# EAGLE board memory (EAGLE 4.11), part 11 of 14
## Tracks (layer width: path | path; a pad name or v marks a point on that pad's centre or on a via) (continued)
N$195  (via drill 0.61) (continued)
  Top 0.254: v421,46.99 421,45.09 F07.J2 | v360.68,10.79 v360.68,6.98 | v179.71,5.71 174.62,10.79 174.62,13.97 161.93,26.67 v161.93,77.47
  Route2 0.254: v421,46.99 423.55,46.99 F07.H2
  Route3 0.254: v422.27,9.52 422.27,42.55 421,43.82 F07.J2 | v87.63,78.74 85.72,80.64 85.72,83.82 v83.82,85.72 | v50.8,113.03 50.8,145.41 53.98,148.59 53.98,214 50.8,217.17 50.8,220.34 v52.07,221.61
  Bottom 0.254: C39.R2 14.61,231.14 14.61,226.69 15.24,226.69 17.14,224.79 17.14,222.88 C39.U2 17.78,221.61 20.32,221.61 23.5,218.44 26.04,220.98 33.66,220.98 34.29,220.34 43.18,220.34 46.99,224.16 49.53,224.16 v52.07,221.61 | v422.27,9.52 421,8.25 403.86,8.25 401.95,6.35 394.97,6.35 394.33,5.71 379.1,5.71 377.82,6.98 v360.68,6.98 | v360.68,10.79 360.05,10.16 332.74,10.16 332.11,10.79 328.3,10.79 327.66,10.16 318.13,10.16 317.5,10.79 291.46,10.79 290.83,10.16 260.99,10.16 260.35,10.79 257.81,10.79 255.91,8.89 247.01,8.89 246.38,9.52 244.47,7.62 220.98,7.62 220.34,6.98 205.74,6.98 205.1,6.35 180.34,6.35 v179.71,5.71 | v161.93,77.47 160.66,78.74 v87.63,78.74 | v83.82,85.72 66.67,102.87 59.69,102.87 59.05,103.5 54.61,103.5 50.8,107.31 v50.8,113.03
N$196  (via drill 0.61)
  Route2 0.254: v373.38,37.46 382.27,46.36 388.62,46.36 394.97,52.7 403.86,52.7 404.5,52.07 413.38,52.07 417.83,56.52 420.37,56.52 F07.D2
  Route3 0.254: v233.68,8.89 233.68,7.62 205.1,7.62 199.39,1.9 141.6,1.9 53.98,89.53 53.98,105.41 60.33,111.76 60.33,114.93 59.05,116.2 59.05,116.84 60.33,118.11 60.33,143.51 63.5,146.69 63.5,200.66 64.14,201.29 64.14,209.55 63.5,210.19 63.5,254.63 60.33,257.81 60.33,280.67 57.15,283.85 57.15,293.37 55.88,294.64 B36.S2 | v255.91,10.16 259.08,10.16 259.08,9.52 260.35,8.25 307.34,8.25 309.88,10.79 327.02,10.79 327.02,16.51 330.83,20.32 337.19,20.32 344.17,27.3 353.06,27.3 353.69,26.67 362.58,26.67 v373.38,37.46
  Bottom 0.254: v233.68,8.89 234.31,8.25 243.84,8.25 245.75,10.16 v255.91,10.16
N$197  (via drill 0.61)
  Top 0.254: v316.23,5.08 311.15,10.16 311.15,35.56 309.88,36.83 309.88,40.64 F16.K2
  Route3 0.254: v375.29,5.08 379.73,0.63 421,0.63 421,10.16 415.93,15.24 415.93,37.46 419.1,40.64 419.1,48.9 417.83,50.16 v417.83,50.8
  Bottom 0.254: v316.23,5.08 316.87,5.71 341.63,5.71 342.9,4.44 374.65,4.44 v375.29,5.08 | v417.83,50.8 420.37,50.8 F07.F2
N$198
  Bottom 0.254: A05.F2 446.4,394.34 446.4,398.15 454.66,398.15 455.3,398.78 464.19,398.78 464.82,398.15 467.36,398.15 468,398.78 476.88,398.78 477.52,398.15 480.06,398.15 481.33,399.42 483.87,399.42 A02.D2
N$200
  Bottom 0.254: B36.L2 52.7,311.79 53.98,313.06 60.96,313.06 61.59,312.42 70.48,312.42 71.12,313.06 73.66,313.06 74.3,312.42 83.19,312.42 83.82,313.06 86.36,313.06 87.63,311.79 90.17,311.79 B33.L2
N$201  (via drill 0.61)
  Top 0.254: v58.42,344.17 57.15,342.9 57.15,326.39 56.52,325.75 56.52,321.95 55.88,321.31 B36.H2 | v20.95,346.08 20.32,346.71 20.32,350.52 19.05,351.79 19.05,384.81 v17.78,386.08
  Bottom 0.254: v58.42,344.17 57.78,343.54 23.5,343.54 v20.95,346.08 | v17.78,386.08 15.24,388.62 8.89,388.62 4.45,393.06 1.91,393.06 A40.F2
N$202
  Top 0.254: A37.M2 42.55,378.46 41.27,379.73 41.27,398.15 40.01,399.42 A37.D2
N$203  (via drill 0.61)
  Top 0.254: v246.38,368.3 244.47,370.21 244.47,407.04 v241.94,409.58
  Route2 0.254: v246.38,368.3 251.46,363.22 254.63,363.22 255.27,362.59 A20.T2 | v202.56,410.85 199.39,414.02 191.13,414.02 190.5,414.66 170.81,414.66 163.83,407.67 161.29,407.67 158.12,410.85 151.76,410.85 150.5,412.12 139.06,412.12 137.79,413.39 67.94,413.39 45.72,391.16 43.18,391.16 A37.H2
  Bottom 0.254: v241.94,409.58 240.03,411.48 203.2,411.48 v202.56,410.85
N$204  (via drill 0.61)
  Top 0.254: v422.27,346.71 422.27,391.8 421,393.06 A07.F2 | v480.69,350.52 483.87,353.7 483.87,354.97 A02.V2
  Bottom 0.254: v422.27,346.71 476.88,346.71 v480.69,350.52
N$205  (via drill 0.61)
  Top 0.254: v433.7,370.21 433.7,372.11 431.8,374.02 431.8,385.45 433.07,386.72 A06.J2
  Bottom 0.254: v433.7,370.21 441.96,370.21 442.6,369.57 451.49,369.57 455.3,373.38 464.19,373.38 464.82,372.75 467.36,372.75 471.17,376.56 480.06,376.56 481.33,375.29 483.87,375.29 A02.N2
N$206
  Top 0.254: F16.U2 309.25,16.51 309.25,21.59 F16.S2
  Bottom 0.254: F15.T2 318.77,19.69 314.32,19.69 312.42,21.59 309.88,21.59 F16.S2
N$207  (via drill 0.61)
  Top 0.254: v241.3,313.69 241.3,306.71 242.57,305.44 B21.N2 | v257.81,312.42 257.81,309.25 258.44,308.61 B20.M2
  Bottom 0.254: v241.3,313.69 245.75,313.69 B21.K2 246.38,313.69 248.92,313.69 250.19,312.42 v257.81,312.42
N$208  (via drill 0.61)
  Route3 0.254: v373.38,225.42 373.38,222.88 C11.U2 | v351.15,227.33 349.25,229.23 349.25,278.77 347.98,280.04 347.98,284.48 349.25,285.75 349.25,296.55 346.07,299.72 346.07,306.07 347.35,307.34 B13.M2
  Bottom 0.254: v373.38,225.42 372.11,226.69 364.49,226.69 363.86,227.33 354.96,227.33 354.33,226.69 351.79,226.69 v351.15,227.33
N$209
  Bottom 0.254: A06.L2 433.7,381.64 434.98,382.91 441.96,382.91 442.6,382.27 451.49,382.27 455.3,386.08 464.19,386.08 468,382.27 476.88,382.27 477.52,382.91 478.15,382.91 487.05,374.02 487.05,372.11 A02.P2
N$210  (via drill 0.61)
  Top 0.254: v346.07,53.98 346.07,53.34 349.25,50.16 349.25,34.29 348.62,33.66 348.62,29.84 347.98,29.21 F13.P2
  Route3 0.254: v346.07,53.98 346.07,83.18 v341.63,87.63
  Bottom 0.254: v341.63,87.63 342.26,86.99 353.06,86.99 353.69,87.63 362.58,87.63 363.22,86.99 365.76,86.99 366.39,87.63 375.29,87.63 379.1,83.82 379.73,83.82 382.9,86.99 391.16,86.99 395.61,91.44 398.14,91.44 E09.S2
N$211  (via drill 0.61)
  Top 0.254: v309.25,30.48 309.25,34.29 F16.M2
  Route3 0.254: v300.99,28.58 295.27,22.86 295.27,20.95 294,19.69 F17.T2
  Bottom 0.254: v300.99,28.58 302.89,30.48 v309.25,30.48
N$212  (via drill 0.61)
  Top 0.254: v377.19,46.36 377.82,46.99 v377.82,70.48 | v394.97,70.48 394.97,81.91 E09.V2
  Bottom 0.254: v377.19,46.36 369.57,46.36 365.76,42.55 363.22,42.55 362.58,43.18 353.69,43.18 353.06,42.55 348.62,42.55 347.98,41.91 F13.K2 | v377.82,70.48 v394.97,70.48
N$213
  Route2 0.254: A06.N2 433.7,374.02 434.98,372.75 439.42,372.75 445.77,366.4 454.66,366.4 458.47,370.21 467.36,370.21 468,369.57 476.88,369.57 477.52,370.21 480.06,370.21 481.33,368.94 483.87,368.94 A02.R2
N$214
  Bottom 0.254: F17.F2 294,51.44 294.64,52.07 299.08,52.07 299.72,52.7 302.26,52.7 302.89,52.07 304.17,52.07 305.44,53.34 309.25,53.34 F16.E2
N$215  (via drill 0.61)
  Top 0.254: v297.81,39.37 301.62,43.18 v301.62,44.45
  Route3 0.254: v297.81,39.37 297.81,36.2 297.18,35.56 F17.M2
  Bottom 0.254: v301.62,44.45 302.89,45.72 307.98,45.72 309.25,46.99 F16.H2
N$216  (via drill 0.61)
  Top 0.254: v436.25,351.79 436.25,348.62 434.98,348.62 433.7,349.89 433.7,354.97 A06.V2
  Bottom 0.254: v436.25,351.79 436.88,351.16 454.02,351.16 455.3,352.43 482.6,352.43 483.87,351.16 494.03,351.16 496.57,353.7 496.57,354.33 495.94,354.33 492.12,358.14 487.68,358.14 A02.U2
N$217  (via drill 0.61)
  Top 0.254: v325.12,73.66 327.02,75.56 327.02,99.06 v328.3,100.33 | v350.52,103.5 353.69,106.68 357.5,106.68 v357.5,104.14
  Route2 0.254: v314.32,67.31 309.25,62.23 306.7,62.23 306.7,57.79 F16.D2 | v357.5,104.14 359.41,102.23 359.41,100.33 360.68,100.33 361.95,101.6 361.95,103.5 365.76,103.5 366.39,102.87 368.3,102.87 371.48,106.04 376.56,106.04 381,110.49 381,118.74 389.89,118.74 v391.8,120.65
  Route3 0.254: v314.32,67.31 315.6,68.58 v315.6,74.29
  Bottom 0.254: v315.6,74.29 316.23,74.93 323.85,74.93 v325.12,73.66 | v328.3,100.33 334.64,100.33 337.82,103.5 340.36,103.5 341,102.87 349.88,102.87 v350.52,103.5 | v391.8,120.65 394.97,120.65 E09.F2
N$218  (via drill 0.61)
  Top 0.254: v417.19,83.18 415.93,84.45 415.93,97.16 414.02,99.06 v414.02,99.69
  Route2 0.254: v309.88,64.13 309.25,64.77 301.62,64.77 301.62,57.15 302.89,55.88 306.07,55.88 306.07,51.44 F16.F2 | v311.79,76.83 315.6,73.02 317.5,73.02 319.4,74.93 327.02,74.93 328.93,73.02 335.28,73.02 337.82,75.56 353.06,75.56 354.33,74.29 372.11,74.29 373.38,75.56 409.57,75.56 v417.19,83.18
  Route3 0.254: v309.88,64.13 312.42,66.67 312.42,76.2 v311.79,76.83 | v401.95,97.16 400.69,98.42 400.69,100.33 400.05,100.96 400.05,106.04 398.78,107.31 398.78,110.49 E09.K2
  Bottom 0.254: v414.02,99.69 408.31,99.69 405.13,96.52 402.59,96.52 v401.95,97.16
N$219  (via drill 0.61)
  Top 0.254: v276.86,5.08 269.88,12.06 269.88,36.2 268.61,37.46 F19.L2 | v329.56,4.44 v336.55,11.43 | v381,13.97 381,36.2 v381.63,36.83 | v382.27,65.41 382.9,66.04 v382.9,76.83
  Route3 0.254: v276.86,5.08 280.67,5.08 280.67,4.44 282.57,2.54 284.48,2.54 285.12,3.17 323.21,3.17 323.21,4.44 324.49,5.71 329.56,5.71 v329.56,4.44 | v381.63,36.83 381,37.46 381,64.13 v382.27,65.41 | v382.9,76.83 384.18,78.1 384.18,106.04 382.9,107.31 E10.L2
  Bottom 0.254: v336.55,11.43 337.19,10.79 359.41,10.79 363.22,14.61 365.76,14.61 366.39,13.97 375.29,13.97 375.92,14.61 378.46,14.61 379.1,13.97 v381,13.97
N$220  (via drill 0.61)
  Route3 0.254: v435.61,331.47 431.8,335.28 431.8,359.41 425.45,365.76 425.45,386.72 421,386.72 A07.J2
  Bottom 0.254: v435.61,331.47 438.79,328.3 441.96,328.3 442.6,328.93 451.49,328.93 452.12,328.3 454.66,328.3 455.3,328.93 464.19,328.93 464.82,328.3 465.45,328.3 466.73,329.56 469.9,329.56 471.17,328.3 478.79,328.3 480.06,329.56 483.87,329.56 B02.D2
N$221  (via drill 0.61)
  Top 0.254: v318.13,68.58 317.5,67.94 317.5,41.91 321.94,41.91 F15.K2 | v334.01,68.58 334.01,84.45 333.38,85.09 333.38,86.36 v335.28,88.27 | v369.57,97.79 369.57,100.96 E11.N2
  Bottom 0.254: v318.13,68.58 v334.01,68.58 | v335.28,88.27 341,93.98 349.88,93.98 350.52,93.34 353.06,93.34 356.87,97.16 365.76,97.16 366.39,96.52 368.3,96.52 v369.57,97.79
N$222  (via drill 0.61)
  Route2 0.254: v337.82,92.07 339.73,93.98 349.88,93.98 350.52,93.34 353.06,93.34 356.87,97.16 365.76,97.16 366.39,96.52 367.03,96.52 370.2,99.69 377.19,99.69 378.46,100.96 382.27,100.96 E10.N2
  Route3 0.254: v274.95,47.62 279.4,52.07 279.4,78.74 282.57,81.91 v282.57,88.9
  Bottom 0.254: v274.95,47.62 271.78,47.62 F19.H2 | v282.57,88.9 284.48,90.8 289.56,90.8 290.19,90.17 297.81,90.17 299.72,92.07 300.99,92.07 302.89,90.17 311.79,90.17 312.42,90.8 314.96,90.8 315.6,90.17 324.49,90.17 325.12,90.8 327.66,90.8 328.3,90.17 335.92,90.17 v337.82,92.07
N$223  (via drill 0.61)
  Route3 0.254: v243.21,288.29 243.21,286.39 B21.V2
  Bottom 0.254: v243.21,288.29 245.11,290.2 251.46,290.2 252.73,291.47 255.27,291.47 B20.T2
N$224
  Bottom 0.254: A06.T2 433.7,362.59 434.98,363.86 441.96,363.86 442.6,363.22 451.49,363.22 452.12,363.86 454.66,363.86 455.3,363.22 464.19,363.22 468,367.03 469.26,367.03 472.44,363.86 480.06,363.86 481.33,362.59 483.87,362.59 A02.T2
N$225  (via drill 0.61)
  Top 0.254: v321.31,29.84 321.94,30.48 321.94,34.29 F15.M2
  Bottom 0.254: v321.31,29.84 320.68,30.48 315.6,30.48 314.96,29.84 310.51,29.84 309.88,29.21 F16.P2
N$226  (via drill 0.61)
  Top 0.254: v434.98,349.89 434.98,366.4 433.7,367.67 A06.R2
  Bottom 0.254: v434.98,349.89 435.61,350.52 454.66,350.52 455.93,351.79 480.69,351.79 481.96,350.52 494.67,350.52 498.48,354.33 498.48,363.22 491.49,363.22 490.22,364.49 487.68,364.49 A02.S2
N$227  (via drill 0.61)
  Route2 0.254: v306.07,20.95 314.96,20.95 315.6,20.32 317.5,20.32 v318.77,21.59
  Route3 0.254: v284.48,19.05 284.48,16.51 F18.U2 | v369.57,22.86 377.82,31.12 377.82,31.75 v379.1,33.02 | v391.16,38.1 393.7,40.64 393.7,83.82 395.61,85.72 395.61,86.99 396.88,88.27 396.88,99.69 395.61,100.96 E09.N2
  Bottom 0.254: v284.48,19.05 285.12,19.69 285.75,19.69 287.02,20.95 289.56,20.95 290.19,20.32 299.08,20.32 299.72,20.95 302.26,20.95 302.89,20.32 305.44,20.32 v306.07,20.95 | v318.77,21.59 319.4,20.95 323.85,20.95 324.49,21.59 327.02,21.59 328.3,20.32 337.19,20.32 337.82,20.95 340.36,20.95 341,20.32 349.88,20.32 350.52,20.95 353.06,20.95 353.69,20.32 362.58,20.32 363.22,20.95 365.76,20.95 366.39,20.32 367.03,20.32 v369.57,22.86 | v379.1,33.02 386.08,33.02 v391.16,38.1
N$228  (via drill 0.61)
  Top 0.254: v214.63,13.97 215.9,15.24 215.9,26.03 219.07,29.21 219.07,34.92 217.81,36.2 217.81,37.46 F23.L2 | v75.56,9.52 57.15,9.52 57.15,1.9 55.88,0.63 3.17,0.63 3.17,26.67 4.45,27.94 F40.P2
  Bottom 0.254: F40.P2 4.45,29.21 2.54,31.12 1.91,31.12 F40.N2 | v214.63,13.97 212.09,13.97 211.46,14.61 202.56,14.61 201.93,13.97 199.39,13.97 198.75,14.61 189.87,14.61 189.23,13.97 186.69,13.97 186.06,14.61 179.07,14.61 178.44,13.97 173.99,13.97 170.18,17.78 162.56,17.78 158.75,13.97 148.59,13.97 147.96,14.61 139.06,14.61 138.43,13.97 137.79,13.97 136.53,15.24 133.35,15.24 132.72,14.61 126.36,14.61 121.28,9.52 v75.56,9.52
N$229  (via drill 0.61)
  Route2 0.254: v313.06,76.83 314.32,75.56 328.93,75.56 332.11,78.74 349.88,78.74 350.52,79.38 354.96,79.38 356.24,78.1 375.29,78.1 v379.1,81.91
  Route3 0.254: v313.06,76.83 313.06,65.41 317.5,60.96 317.5,59.05 318.77,57.79 F15.D2 | v410.85,93.98 412.75,95.88 412.75,123.19 419.1,129.54 419.1,144.14 421,146.05 v421,147.32
  Bottom 0.254: v379.1,81.91 381.63,84.45 387.35,84.45 387.99,85.09 390.52,85.09 391.8,83.82 400.05,83.82 410.21,93.98 v410.85,93.98 | v421,147.32 431.8,147.32 433.07,148.59 D06.V2
N$230  (via drill 0.61)
  Top 0.254: v43.81,26.67 66.67,49.53 v66.67,70.48 | v74.3,70.48 76.2,72.39 76.2,138.43 78.11,140.34 78.11,146.05 79.38,147.32 80.64,146.05 v80.64,144.78
  Route3 0.254: v80.64,144.78 81.28,145.41 81.28,147.95 79.38,149.86 79.38,213.36 73.03,219.71 73.03,300.36 69.85,303.53 69.85,367.67 66.67,370.84 66.67,394.97 67.94,396.24 A35.E2
  Bottom 0.254: v43.81,26.67 36.2,26.67 35.56,27.3 33.02,27.3 32.38,26.67 23.5,26.67 22.86,27.3 16.51,27.3 10.16,33.66 5.71,33.66 5.08,34.29 F40.M2 | v66.67,70.48 v74.3,70.48
N$231
  Top 0.254: F38.M2 29.84,35.56 29.21,36.2 29.21,40.01 28.57,40.64 28.57,55.25 27.3,56.52 F38.D2
N$232
  Bottom 0.254: A11.K2 373.38,384.81 374.01,385.45 378.46,385.45 379.1,386.08 387.99,386.08 388.62,385.45 391.16,385.45 392.43,386.72 394.97,386.72 A09.J2
N$233  (via drill 0.61)
  Top 0.254: v34.92,281.31 v34.92,176.53 | v200.03,281.94 200.03,383.54 195.58,387.99 | 195.58,387.99 195.58,389.89 A25.H2 | 195.58,387.99 192.41,387.99 A25.J2
  Bottom 0.254: v34.92,176.53 28.57,176.53 27.3,175.26 D38.L2 | v34.92,281.31 57.15,281.31 57.78,281.94 159.38,281.94 160.02,282.58 199.39,282.58 v200.03,281.94
N$234  (via drill 0.61)
  Route3 0.254: v426.72,98.42 428.62,96.52 428.62,92.71 422.27,86.36 422.27,70.48 419.74,67.94 419.74,64.77 419.1,64.13 419.1,50.16 458.47,10.79 483.87,10.79 483.87,12.06 F02.V2
  Bottom 0.254: v426.72,98.42 425.45,99.69 422.27,99.69 421,100.96 E07.N2
N$235
  Top 0.254: F37.M2 42.55,35.56 41.27,36.83 41.27,55.25 40.01,56.52 F37.D2
N$236  (via drill 0.61)
  Top 0.254: v5.08,58.42 6.35,59.69 v6.35,176.53 | D39.F2 14.61,186.69 15.88,185.42 15.88,179.7 17.14,178.44 D39.K2
  Bottom 0.254: v5.08,58.42 2.54,55.88 1.91,55.88 1.91,51.44 F40.F2 | v6.35,176.53 9.53,179.7 12.06,179.7 13.34,178.44 17.14,178.44 D39.K2
N$237
  Bottom 0.254: C40.F2 1.91,256.54 3.81,254.63 4.45,254.63 C40.H2
N$238  (via drill 0.61)
  Top 0.254: C38.J2 26.67,251.46 26.67,256.54 C38.F2 | v15.88,71.12 15.88,55.25 12.7,52.07 12.7,10.79 7.62,10.79 6.35,12.06 6.35,13.97 5.08,15.24 F40.U2
  Route2 0.254: v43.18,226.06 28.57,240.66 28.57,250.19 27.3,250.19 C38.J2
  Route3 0.254: v46.35,76.2 47.62,77.47 47.62,134.62 45.09,137.16 45.09,147.95 44.45,148.59 44.45,224.79 v43.18,226.06
  Bottom 0.254: F40.V2 1.91,13.34 3.81,15.24 4.45,15.24 F40.U2 | v15.88,71.12 20.95,76.2 v46.35,76.2
N$239
  Route2 0.254: D37.J2 40.01,180.34 41.91,178.44 42.55,178.44 D37.K2
N$240
  Top 0.254: D37.T2 40.01,155.57 42.55,155.57 42.55,158.11 D37.S2
N$241
  Top 0.254: F06.S2 436.25,21.59 434.98,20.32 434.98,18.41 427.36,10.79 422.27,10.79 422.27,33.02 423.55,34.29 F07.M2
N$242  (via drill 0.61)
  Top 0.254: v147.96,212.72 151.13,215.9 v151.13,218.44 | v214,231.78 215.9,233.68 v215.9,234.31
  Route2 0.254: v90.81,182.88 90.81,186.06 92.08,186.06 101.6,195.58 111.76,195.58 112.39,194.94 113.67,194.94 122.56,203.84 122.56,212.09 135.25,212.09 135.89,212.72 v147.96,212.72 | v151.13,218.44 156.21,223.52 162.56,223.52 163.19,224.16 172.09,224.16 172.72,223.52 175.26,223.52 175.9,224.16 182.25,224.16 185.42,227.33 187.96,227.33 188.59,226.69 197.49,226.69 198.12,227.33 200.03,227.33 201.93,225.42 202.56,225.42 207.01,229.87 212.09,229.87 v214,231.78 | v215.9,234.31 216.53,233.68 226.06,233.68 226.69,233.04 229.24,233.04 232.41,236.22 238.12,236.22 241.3,239.39 248.28,239.39 255.27,246.38 264.16,246.38 264.8,245.75 273.05,245.75 280.04,252.73 286.38,252.73 287.65,254 288.29,254 290.19,252.09 295.27,252.09 297.18,250.19 298.45,250.19 302.89,245.75 v309.25,245.75 | v341,250.19 344.81,254 345.44,254 346.71,252.73 353.06,252.73 353.69,252.09 360.05,252.09 363.22,248.92 365.76,248.92 366.39,249.56 370.84,249.56 372.75,251.46 372.75,253.36 C11.H2
  Bottom 0.254: v90.81,182.88 90.17,182.88 60.96,153.67 53.98,153.67 52.7,154.94 D36.T2 | v309.25,245.75 309.88,246.38 314.96,246.38 315.6,245.75 323.85,245.75 328.93,250.82 329.56,250.82 331.47,248.92 339.73,248.92 v341,250.19
N$243
  Top 0.254: A39.K2 17.14,384.81 15.88,386.08 15.88,391.8 14.61,393.06 A39.F2
  Bottom 0.254: A38.F2 26.67,393.06 26.67,388.62 24.13,388.62 20.32,384.81 17.78,384.81 A39.K2
N$244  (via drill 0.61)
  Top 0.254: v75.56,45.72 79.38,49.53 v79.38,146.05 | v57.15,161.29 v57.15,146.05 | v39.37,223.52 41.27,221.61 41.27,217.81 38.73,215.26 38.73,203.2 v40.01,201.93
  Route2 0.254: v40.01,201.93 50.8,191.13 50.8,162.56 52.07,162.56 D36.R2
  Route3 0.254: v24.13,354.33 31.75,346.71 31.75,323.22 38.1,316.87 38.1,296.55 39.37,295.28 39.37,294 38.1,292.74 38.1,238.12 36.83,236.85 38.1,235.59 38.1,224.79 v39.37,223.52
  Bottom 0.254: v75.56,45.72 74.3,45.72 70.48,49.53 61.59,49.53 60.96,48.9 56.52,48.9 55.88,48.26 F36.H2 | v57.15,146.05 v79.38,146.05 | v57.15,161.29 52.7,161.29 D36.R2 | v24.13,354.33 8.26,370.21 1.91,370.21 1.91,374.02 A40.N2
N$245  (via drill 0.61)
  Top 0.254: v328.3,224.16 328.3,226.69 327.02,227.97 v327.02,254
  Route3 0.254: v419.1,92.07 419.1,113.03 v414.02,118.11 | v389.25,122.55 387.35,124.46 387.35,167.64 384.18,170.81 384.18,173.99 387.35,177.16 387.35,184.78 v385.44,186.69 | v341.63,187.32 336.55,192.41 v336.55,218.44
  Bottom 0.254: v327.02,254 322.58,254 C15.H2 | C15.V2 319.4,219.71 320.68,220.98 323.85,220.98 325.75,222.88 327.02,222.88 v328.3,224.16 336.55,224.16 v336.55,218.44 | v419.1,92.07 421,90.17 423.55,90.17 423.55,86.36 E07.U2 | v414.02,118.11 410.21,121.92 402.59,121.92 401.95,122.55 393.06,122.55 392.43,121.92 389.89,121.92 v389.25,122.55 | v385.44,186.69 384.81,186.06 377.19,186.06 376.56,185.42 367.67,185.42 367.03,186.06 364.49,186.06 363.86,185.42 354.96,185.42 354.33,186.06 351.79,186.06 351.15,185.42 343.54,185.42 v341.63,187.32
N$246  (via drill 0.61)
  Top 0.254: v319.4,234.95 317.5,236.85 317.5,248.92 318.77,250.19 C15.J2
  Route2 0.254: v319.4,234.95 321.94,234.95 C15.P2
N$247
  Top 0.254: B18.F2 281.31,323.22 281.94,322.58 281.94,318.77 282.57,318.14 282.57,268.61 281.31,267.34 281.31,264.16 C18.D2 | C18.U2 283.85,222.88 282.57,224.16 282.57,235.59 281.31,236.85 281.31,237.49 C18.N2 | 320.68,245.75 321.94,247.01 C15.K2 | 320.68,245.75 320.68,240.03 | 320.68,240.03 319.4,238.76 C15.N2 | 320.68,245.75 320.68,257.81 320.04,258.44 320.04,262.25 319.4,262.89 C15.D2 | 320.68,240.03 320.68,227.97 321.31,227.33 321.31,223.52 321.94,222.88 C15.U2
  Bottom 0.254: C20.D2 255.91,264.16 257.18,265.43 262.89,265.43 264.8,263.53 267.97,263.53 C19.D2 268.61,264.16 269.88,265.43 275.59,265.43 277.5,263.53 280.67,263.53 C18.D2 281.31,264.16 282.57,265.43 287.65,265.43 289.56,263.53 293.37,263.53 C17.D2 294,264.16 298.45,264.16 299.72,265.43 300.99,265.43 302.89,263.53 306.07,263.53 C16.D2 306.7,264.16 307.98,265.43 313.69,265.43 315.6,263.53 318.77,263.53 C15.D2 | C20.U2 259.08,221.61 259.71,220.98 264.16,220.98 264.8,220.34 269.88,220.34 271.14,221.61 C19.U2 271.78,221.61 274.32,221.61 275.59,220.34 282.57,220.34 283.85,221.61 C18.U2 | C20.N2 255.91,237.49 257.18,236.22 263.52,236.22 265.43,238.12 267.97,238.12 C19.N2 268.61,237.49 269.88,236.22 276.86,236.22 278.13,237.49 280.67,237.49 C18.N2 281.31,237.49 282.57,236.22 289.56,236.22 290.83,237.49 293.37,237.49 C17.N2 294,237.49 295.27,236.22 301.62,236.22 303.53,238.12 306.07,238.12 C16.N2 306.7,237.49 311.15,237.49 312.42,236.22 313.06,236.22 314.32,237.49 318.77,237.49 C15.N2 | C20.K2 259.08,247.01 263.52,247.01 264.8,245.75 269.88,245.75 271.14,247.01 C19.K2 271.78,247.65 274.32,247.65 276.23,249.56 278.13,249.56 279.4,248.28 283.85,248.28 C18.K2 284.48,247.65 288.29,247.65 290.19,249.56 293.37,249.56 295.27,247.65 296.55,247.65 C17.K2 297.18,248.28 301.62,248.28 302.89,249.56 303.53,249.56 304.8,248.28 309.25,248.28 C16.K2 309.88,248.28 310.51,248.92 314.96,248.92 315.6,249.56 320.68,249.56 321.94,248.28 C15.K2 | C17.U2 297.18,222.88 301.62,222.88 302.89,224.16 303.53,224.16 304.8,222.88 309.25,222.88 C16.U2 309.88,222.88 312.42,222.88 313.69,224.16 316.23,224.16 318.13,222.25 321.94,222.25 C15.U2
N$248  (via drill 0.61)
  Top 0.254: C16.H2 309.88,253.36 311.15,252.09 311.15,234.31 307.98,231.14 307.98,224.79 307.34,224.16 307.34,220.34 306.7,219.71 C16.V2 306.7,218.44 306.7,209.55 v309.88,206.38
  Route2 0.254: v412.75,207.01 411.48,208.28 391.8,208.28 390.52,209.55 321.31,209.55 v319.4,207.64
  Route3 0.254: v455.93,154.94 454.02,156.84 v454.02,158.11 | v427.36,165.73 428.62,167 428.62,179.7 429.89,180.97 429.89,182.25 428.62,183.51 428.62,201.29 v426.72,203.2
  Bottom 0.254: v455.93,154.94 457.2,153.67 465.45,153.67 466.09,154.31 473.07,154.31 474.35,153.03 D03.U2 | v454.02,158.11 451.49,160.66 440.69,160.66 440.06,160.02 433.07,160.02 v427.36,165.73 | v426.72,203.2 424.81,205.1 416.56,205.1 414.65,207.01 v412.75,207.01 | v319.4,207.64 313.06,207.64 311.79,206.38 v309.88,206.38
N$249
  Top 0.254: C16.P2 309.25,235.59 307.98,236.85 307.98,248.92 306.7,250.19 C16.J2
N$250  (via drill 0.61)
  Top 0.254: v461.01,375.92 463.55,373.38 463.55,327.03 v464.82,325.75
  Bottom 0.254: v461.01,375.92 455.3,375.92 454.66,376.56 447.04,376.56 443.87,379.73 442.6,379.73 441.96,379.1 431.8,379.1 431.17,379.73 429.89,379.73 429.26,379.1 422.27,379.1 421,380.37 A07.L2 | v464.82,325.75 467.36,325.75 468,325.12 476.88,325.12 480.69,328.93 485.77,328.93 487.05,327.66 B02.E2
N$251  (via drill 0.61)
  Top 0.254: v288.93,219.07 v288.93,250.82
  Route2 0.254: v288.93,219.07 293.37,219.07 C17.V2 294,219.07 297.18,219.07 300.99,215.26 396.24,215.26 397.51,216.53 414.02,216.53 421,223.52 427.99,223.52 v429.89,225.42
  Bottom 0.254: v288.93,250.82 290.19,252.09 294,252.09 295.91,254 296.55,254 C17.H2 | v429.89,225.42 433.07,228.6 436.25,228.6 C06.S2
N$252
  Top 0.254: C17.P2 296.55,235.59 295.27,236.85 295.27,247.65 294,248.92 294,250.19 C17.J2
N$253  (via drill 0.61)
  Top 0.254: v418.46,366.4 418.46,368.3 419.74,369.57 419.74,373.38 420.37,374.02 A07.N2 | v477.52,358.78 479.43,356.87 479.43,320.04 483.24,316.23 485.77,316.23 485.77,321.31 484.5,322.58 484.5,323.22 B02.F2
  Bottom 0.254: v418.46,366.4 421,363.86 429.26,363.86 433.07,360.05 441.96,360.05 442.6,360.68 451.49,360.68 452.12,360.05 454.66,360.05 455.3,360.68 464.19,360.68 464.82,360.05 467.36,360.05 468,360.68 475.62,360.68 v477.52,358.78
N$254  (via drill 0.61)
  Top 0.254: C18.V2 280.67,219.71 279.4,220.98 279.4,251.46 281.31,253.36 283.85,253.36 C18.H2 283.85,254.63 283.85,256.54 282.57,257.81 282.57,267.34 283.21,267.97 283.21,269.88 v284.48,271.15
  Route2 0.254: v396.88,283.85 394.33,281.31 377.82,281.31 374.01,277.5 353.06,277.5 352.43,276.86 315.6,276.86 314.32,275.59 305.44,275.59 304.8,274.96 288.29,274.96 v284.48,271.15
  Route3 0.254: v429.89,292.1 431.8,294 431.8,295.91 430.53,297.18 430.53,297.81 431.8,299.09 431.8,318.14 434.98,321.31 434.98,325.12 436.25,326.39 B06.E2
  Bottom 0.254: v429.89,292.1 421.64,283.85 v396.88,283.85
N$255
  Top 0.254: C18.P2 283.85,235.59 282.57,236.85 282.57,248.92 281.31,250.19 C18.J2
N$256  (via drill 0.61)
  Top 0.254: v483.24,347.35 488.95,341.63 488.95,316.23 487.68,314.96 B02.K2
  Route2 0.254: v483.24,347.35 480.69,347.35 480.06,347.98 450.85,347.98 445.77,353.06 422.91,353.06 421,354.97 A07.V2
N$257  (via drill 0.61)
  Top 0.254: v267.97,234.31 269.88,232.41 269.88,220.98 268.61,219.71 C19.V2 | v265.43,236.85 266.06,237.49 266.06,240.03 266.7,240.66 266.7,251.46 268.61,253.36 271.14,253.36 C19.H2 | v392.43,303.53 391.8,303.53 390.52,302.26 v390.52,280.04 | v325.75,275.59 v325.75,280.67
  Route2 0.254: v265.43,236.85 v267.97,234.31 | v375.92,280.67 374.65,281.94 368.3,281.94 367.67,281.31 361.31,281.31 360.05,282.58 327.66,282.58 v325.75,280.67 | v325.75,275.59 325.12,274.96 313.69,274.96 307.34,268.61 300.99,268.61 300.36,267.97 295.27,267.97 v294,266.7
  Route3 0.254: v425.45,313.69 425.45,363.22 424.18,364.49 A07.S2 | v294,266.7 288.93,261.62 288.93,254 v287.65,252.73
  Bottom 0.254: v425.45,313.69 424.18,312.42 417.83,312.42 411.48,306.07 405.13,306.07 401.95,302.9 393.06,302.9 v392.43,303.53 | v390.52,280.04 389.25,281.31 376.56,281.31 v375.92,280.67 | v287.65,252.73 278.76,252.73 278.13,252.09 276.86,252.09 274.95,254 271.78,254 C19.H2
N$258
  Top 0.254: C19.J2 268.61,250.19 269.88,248.92 269.88,236.85 271.14,235.59 C19.P2
N$259  (via drill 0.61)
  Top 0.254: v419.74,347.98 419.1,348.62 419.1,360.05 420.37,361.31 A07.T2 | v480.69,346.08 482.6,344.17 482.6,319.41 483.87,318.14 B02.J2
  Bottom 0.254: v419.74,347.98 422.27,345.44 448.94,345.44 449.58,346.08 v480.69,346.08
N$260  (via drill 0.61)
  Top 0.254: v421,377.19 419.1,375.29 419.1,370.21 v417.19,368.3 | v263.52,340.36 263.52,314.96 260.35,311.79 v260.35,310.52
  Route2 0.254: v417.19,368.3 415.29,366.4 412.75,366.4 409.57,369.57 402.59,369.57 396.24,375.92 389.89,375.92 389.25,376.56 380.37,376.56 379.73,375.92 377.19,375.92 373.38,379.73 364.49,379.73 360.68,375.92 351.79,375.92 351.15,376.56 342.26,376.56 337.82,372.11 v337.82,371.48 | v293.37,370.21 283.85,360.68 275.59,360.68 269.24,354.33 267.33,354.33 v266.7,354.97
  Route3 0.254: 260.35,252.09 v260.35,219.71 | 260.35,252.09 259.08,253.36 C20.H2 | v266.7,354.97 263.52,351.79 v263.52,340.36 | v260.35,310.52 260.35,295.28 261.62,294 260.35,292.74 260.35,252.09
  Bottom 0.254: v260.35,219.71 259.71,219.07 255.91,219.07 C20.V2 | v421,377.19 423.55,377.19 A07.M2 | v337.82,371.48 336.55,370.21 329.56,370.21 328.93,369.57 326.39,369.57 325.75,370.21 316.87,370.21 313.06,366.4 310.51,366.4 307.34,369.57 300.99,369.57 300.36,370.21 v293.37,370.21
N$261  (via drill 0.61)
  Top 0.254: v254,234.95 254,248.92 255.27,250.19 C20.J2
  Route2 0.254: v254,234.95 258.44,234.95 C20.P2
N$262  (via drill 0.61)
  Top 0.254: v480.69,348.62 485.77,343.54 485.77,322.58 487.05,321.31 B02.H2
  Route2 0.254: v480.69,348.62 475.62,353.7 445.77,353.7 429.26,370.21 422.27,370.21 421,368.94 A07.R2
N$263  (via drill 0.61)
  Top 0.254: v415.93,127.63 415.93,175.89 412.75,179.07 412.75,204.47 v410.21,207.01 | v323.85,207.64 323.21,208.28 323.21,219.07 320.68,221.61 320.68,226.69 319.4,227.97 v319.4,228.6 | v304.8,234.95 304.8,238.76 305.44,239.39 305.44,243.2 306.07,243.84 C16.L2 | v321.94,233.04 321.94,229.23 C15.S2
  Bottom 0.254: v415.93,127.63 417.83,125.73 422.27,125.73 423.55,124.46 E07.E2 | v410.21,207.01 409.57,206.38 383.54,206.38 381.63,208.28 367.67,208.28 366.39,207.01 363.22,207.01 361.95,208.28 360.68,208.28 358.77,206.38 337.82,206.38 337.19,207.01 324.49,207.01 v323.85,207.64 | v319.4,228.6 321.94,228.6 C15.S2 | v304.8,234.95 306.07,233.68 314.96,233.68 315.6,233.04 v321.94,233.04
N$264  (via drill 0.61)
  Route3 0.254: v316.23,225.42 314.32,227.33 314.32,253.36 309.88,257.81 309.88,259.72 C16.E2
  Bottom 0.254: v316.23,225.42 318.77,225.42 C15.T2
N$265  (via drill 0.61)
  Route2 0.254: v393.7,221.61 392.43,220.34 389.89,220.34 389.25,220.98 380.37,220.98 379.73,220.34 377.19,220.34 370.84,226.69 364.49,226.69 363.86,227.33 354.96,227.33 354.33,226.69 353.06,226.69 v351.15,228.6 | v334.64,226.69 327.66,226.69 327.02,227.33 v326.39,227.33
  Route3 0.254: v309.25,243.84 307.98,242.57 307.98,240.66 308.61,240.03 308.61,236.22 307.98,235.59 307.98,230.5 309.25,229.23 C16.S2
  Bottom 0.254: v309.25,243.84 307.34,245.75 300.99,245.75 300.36,246.38 299.08,246.38 296.55,243.84 294,243.84 C17.L2 | v393.7,221.61 395.61,223.52 401.95,223.52 402.59,224.16 405.13,224.16 405.76,223.52 414.65,223.52 415.29,224.16 417.83,224.16 418.46,223.52 427.36,223.52 427.99,224.16 434.98,224.16 436.25,222.88 C06.U2 | v351.15,228.6 349.25,226.69 339.09,226.69 338.45,227.33 335.28,227.33 v334.64,226.69 | v326.39,227.33 316.87,227.33 316.23,226.69 313.69,226.69 312.42,227.97 309.88,227.97 C16.S2
N$266  (via drill 0.61)
  Top 0.254: v295.91,227.33 292.1,231.14 292.1,236.22 290.83,237.49 290.83,239.39 292.1,240.66 v292.1,259.72
  Bottom 0.254: v295.91,227.33 300.36,227.33 300.99,226.69 305.44,226.69 306.07,226.06 C16.T2 | v292.1,259.72 296.55,259.72 C17.E2
N$267  (via drill 0.61)
  Top 0.254: v292.1,239.39 292.1,237.49 295.91,233.68 295.91,229.87 296.55,229.23 C17.S2 | v281.31,240.03 281.31,243.84 C18.L2
  Route2 0.254: v403.23,279.4 401.95,278.13 384.81,278.13 382.9,276.23 363.86,276.23 363.22,276.86 360.05,276.86 v347.98,264.8
  Route3 0.254: v410.85,311.79 403.23,304.17 v403.23,279.4 | v290.83,258.44 292.1,257.18 v292.1,239.39
  Bottom 0.254: v292.1,239.39 288.29,239.39 287.65,240.03 v281.31,240.03 | v410.85,311.79 418.46,319.41 427.36,319.41 427.99,318.77 430.53,318.77 432.44,320.68 436.25,320.68 B06.H2 | v347.98,264.8 345.44,262.25 339.09,262.25 338.45,261.62 329.56,261.62 328.93,262.25 326.39,262.25 325.75,261.62 316.87,261.62 316.23,262.25 313.69,262.25 310.51,259.08 304.17,259.08 303.53,258.44 300.99,258.44 300.36,259.08 292.74,259.08 292.1,258.44 v290.83,258.44
N$268  (via drill 0.61)
  Top 0.254: v268.61,229.23 266.7,231.14 266.7,238.76 267.33,239.39 267.33,243.2 267.97,243.84 C19.L2 | v310.51,269.88 307.98,267.34 v307.98,251.46
  Route2 0.254: v268.61,229.23 269.24,229.87 276.86,229.87 277.5,230.5 282.57,230.5 283.85,229.23 C18.S2 | v412.75,351.79 417.83,356.87 422.27,356.87 423.55,358.14 A07.U2 | v375.92,320.68 371.48,316.23 364.49,316.23 363.86,315.6 354.96,315.6 354.33,316.23 353.69,316.23 347.35,309.88 339.09,309.88 335.28,306.07 330.2,306.07 v328.93,304.8 | v341,269.88 339.09,271.78 329.56,271.78 328.93,271.15 326.39,271.15 325.75,271.78 316.87,271.78 313.06,267.97 312.42,267.97 v310.51,269.88 | v295.27,248.92 288.93,242.57 278.76,242.57 278.13,243.2 275.59,243.2 274.95,242.57 269.88,242.57 268.61,243.84 C19.L2
  Route3 0.254: v393.06,349.25 377.82,334.01 377.82,322.58 v375.92,320.68 | v328.93,304.8 332.74,300.99 333.38,300.99 334.64,299.72 334.64,297.18 333.38,295.91 333.38,293.37 344.17,282.58 344.17,273.05 v341,269.88
  Bottom 0.254: v412.75,351.79 410.85,349.89 398.78,349.89 398.14,349.25 v393.06,349.25 | v307.98,251.46 307.98,249.56 304.8,249.56 304.17,250.19 301.62,250.19 300.36,248.92 v295.27,248.92
N$269  (via drill 0.61)
  Route3 0.254: v274.95,227.33 273.05,229.23 273.05,254.63 272.42,255.27 272.42,259.08 271.78,259.72 C19.E2
  Bottom 0.254: v274.95,227.33 276.23,226.06 280.67,226.06 C18.T2
N$270  (via drill 0.61)
  Route3 0.254: v287.65,227.33 285.75,229.23 285.75,258.44 284.48,259.72 C18.E2
  Bottom 0.254: v287.65,227.33 288.93,226.06 293.37,226.06 C17.T2
N$271  (via drill 0.61)
  Top 0.254: v267.97,235.59 271.14,232.41 271.14,229.23 C19.S2 | v265.43,285.75 265.43,274.96 266.7,273.69 266.7,259.08 v264.8,257.18 | v255.27,247.65 255.27,245.11 C20.L2
  Route2 0.254: v267.97,235.59 260.99,242.57 257.18,242.57 255.91,243.84 C20.L2 | v264.8,257.18 v255.27,247.65
  Route3 0.254: v417.19,316.87 419.1,318.77 419.1,344.81 422.27,347.98 422.27,369.57 423.55,370.84 A07.P2 | v265.43,304.8 266.7,303.53 266.7,287.02 v265.43,285.75
  Bottom 0.254: v417.19,316.87 410.21,309.88 402.59,309.88 398.78,306.07 389.89,306.07 389.25,306.71 384.81,306.71 384.18,306.07 377.19,306.07 376.56,306.71 367.67,306.71 367.03,306.07 364.49,306.07 363.86,306.71 354.96,306.71 354.33,306.07 351.79,306.07 351.15,306.71 342.26,306.71 341.63,306.07 339.09,306.07 338.45,306.71 329.56,306.71 328.93,306.07 326.39,306.07 325.75,306.71 316.87,306.71 316.23,306.07 313.69,306.07 313.06,306.71 304.17,306.71 303.53,306.07 300.99,306.07 300.36,306.71 291.46,306.71 287.65,302.9 285.12,302.9 281.94,306.07 275.59,306.07 274.95,306.71 267.33,306.71 v265.43,304.8
N$272  (via drill 0.61)
  Route3 0.254: v269.88,256.54 269.24,255.91 269.24,252.09 269.88,251.46 269.88,227.33 268.61,226.06 C19.T2
  Bottom 0.254: v269.88,256.54 269.24,255.91 267.33,255.91 264.16,259.08 259.71,259.08 259.08,259.72 C20.E2
N$273  (via drill 0.61)
  Top 0.254: v481.33,316.23 485.77,311.79 485.77,309.88 487.05,308.61 B02.M2 | v432.44,321.95 433.07,321.31 433.07,318.14 B06.J2
  Bottom 0.254: v481.33,316.23 478.15,319.41 471.81,319.41 468.63,322.58 468,322.58 464.19,318.77 453.39,318.77 449.58,322.58 440.69,322.58 440.06,321.95 v432.44,321.95
N$274  (via drill 0.61)
  Top 0.254: v435.61,313.06 434.98,313.69 434.98,318.77 433.7,320.04 433.7,323.22 B06.F2
  Bottom 0.254: v435.61,313.06 440.06,313.06 440.69,312.42 443.23,312.42 443.87,313.06 452.75,313.06 453.39,312.42 455.93,312.42 456.56,313.06 465.45,313.06 466.09,312.42 468.63,312.42 469.26,313.06 478.15,313.06 479.43,311.79 483.87,311.79 B02.L2
N$275  (via drill 0.61)
  Top 0.254: v479.43,120.65 479.43,96.52 482.6,93.34 482.6,84.45 483.87,83.18 E02.V2 | v472.44,135.25 471.81,135.89 471.81,148.59 D03.V2
  Bottom 0.254: v479.43,120.65 479.43,128.27 v472.44,135.25
N$276  (via drill 0.61)
  Top 0.254: v450.85,173.99 450.85,183.51 454.02,186.69 454.02,203.2 452.75,204.47 v452.75,210.19 | v433.7,210.19 433.7,218.44 C06.V2
  Route3 0.254: v488.95,117.47 488.95,113.66 492.12,110.49 492.12,86.36 487.68,86.36 E02.U2 | v455.3,138.43 455.93,139.06 455.93,146.05 457.2,147.32 457.2,160.66 450.85,167 v450.85,173.99
  Bottom 0.254: v488.95,117.47 488.95,121.92 492.12,125.09 492.12,131.44 481.96,131.44 474.98,138.43 v455.3,138.43 | v452.75,210.19 437.51,210.19 436.88,210.82 434.34,210.82 v433.7,210.19
N$277  (via drill 0.61)
  Top 0.254: v496.57,212.09 497.84,210.82 497.84,203.2 v496.57,201.93 | v465.45,125.09 464.19,123.82 464.19,121.92 463.55,121.28 463.55,99.06 v468.63,93.98
  Route2 0.254: v494.03,188.59 492.12,186.69 492.12,170.18 490.22,170.18 466.73,146.69 466.73,125.09 v465.45,125.09
  Route3 0.254: v438.15,212.72 434.98,215.9 434.98,223.52 433.7,224.79 C06.T2
  Bottom 0.254: v438.15,212.72 451.49,212.72 452.75,214 483.24,214 485.14,212.09 v496.57,212.09 | v496.57,201.93 495.3,200.66 495.3,188.59 v494.03,188.59 | v468.63,93.98 469.26,93.34 477.52,93.34 481.33,89.53 483.87,89.53 E02.T2
N$278  (via drill 0.61)
  Top 0.254: v488.95,70.48 488.95,55.88 487.68,54.61 F02.E2 | v421,71.75 421,81.91 E07.V2
  Bottom 0.254: v488.95,70.48 487.68,71.75 475.62,71.75 474.98,72.39 421.64,72.39 v421,71.75
N$279  (via drill 0.61)
  Top 0.254: v422.91,69.85 422.27,70.48 422.27,90.17 419.1,93.34 419.1,118.74 420.37,120.02 E07.F2
  Bottom 0.254: v422.91,69.85 423.55,70.48 476.88,70.48 476.88,68.58 483.24,62.23 483.87,62.23 483.87,57.79 F02.D2
N$281  (via drill 0.61)
  Top 0.254: 469.9,109.22 v468,109.22 | 469.9,109.22 v469.9,168.28 469.9,172.72 v468,174.62 | v469.9,46.99 469.9,109.22
  Route3 0.254: v469.9,46.99 463.55,40.64 463.55,24.13 462.28,22.86 F04.S2
  Bottom 0.254: v468,109.22 467.36,109.85 460.38,109.85 459.11,108.58 E04.L2 | v469.9,168.28 469.9,170.81 474.35,170.81 D03.M2 | v468,174.62 466.09,176.53 464.82,176.53 464.19,175.89 455.3,175.89 454.66,176.53 450.21,176.53 449.58,177.16 D05.K2
N$282  (via drill 0.61)
  Top 0.254: v476.25,245.75 476.25,283.21 474.98,284.48 474.98,288.29 B03.U2 | v460.38,167.64 460.38,164.47 461.01,163.83 461.01,160.02 461.64,159.38 D04.S2 | v455.93,169.54 454.66,169.54 454.66,170.18 454.02,170.81 454.02,172.72 456.56,175.26 456.56,176.53 457.2,177.16 457.2,231.14 454.02,234.31 454.02,240.03 452.75,241.3 v452.75,242.57
  Bottom 0.254: D05.U2 449.58,153.03 450.21,153.67 453.39,153.67 457.83,158.11 461.64,158.11 D04.S2 | v476.25,245.75 468,245.75 467.36,246.38 460.38,246.38 459.11,245.11 C04.L2 458.47,243.84 454.02,243.84 v452.75,242.57 | v460.38,167.64 460.38,169.54 v455.93,169.54
N$283  (via drill 0.61)
  Top 0.254: v476.88,320.68 479.43,318.14 479.43,299.09 483.87,299.09 B02.R2
  Bottom 0.254: v476.88,320.68 474.35,323.22 471.81,323.22 B03.F2
N$284  (via drill 0.61)
  Top 0.254: v449.58,132.08 449.58,133.35 447.68,135.25 447.68,169.54 448.94,170.81 D05.M2
  Route2 0.254: v449.58,132.08 459.11,122.55 v460.38,122.55
  Route3 0.254: E04.V2 459.11,83.18 460.38,84.45 460.38,115.57 461.64,116.84 E04.H2
  Bottom 0.254: D05.M2 449.58,172.09 450.21,172.72 454.66,172.72 455.3,173.35 464.19,173.35 464.82,172.72 467.36,172.72 471.81,177.16 474.35,177.16 D03.K2 | v460.38,122.55 460.38,118.11 461.64,118.11 E04.H2
N$285  (via drill 0.61)
  Top 0.254: v448.94,154.31 448.94,158.11 D05.S2 | v474.35,186.06 474.35,189.86 D03.E2
  Route2 0.254: D05.S2 449.58,159.38 449.58,163.83 450.21,163.83 450.85,164.47 450.85,172.72 454.02,172.72 461.64,180.34 461.64,183.51 D04.H2
  Bottom 0.254: v448.94,154.31 447.68,154.31 447.68,151.76 448.31,151.13 452.75,151.13 453.39,150.5 457.83,150.5 458.47,149.86 D04.V2 | v474.35,186.06 468,186.06 467.36,185.42 462.92,185.42 462.28,184.78 D04.H2
N$286  (via drill 0.61)
  Top 0.254: v452.75,97.79 450.85,99.69 450.85,163.19 449.58,164.47 D05.P2 | v454.02,173.99 453.39,173.35 453.39,169.54 454.02,168.91 v454.02,165.1
  Route3 0.254: v459.11,179.07 459.11,175.26 D04.L2
  Bottom 0.254: v459.11,179.07 466.73,179.07 471.81,184.15 474.35,184.15 D03.H2 | v452.75,97.79 456.56,93.98 460.38,93.98 461.64,92.71 E04.S2 | v454.02,173.99 458.47,173.99 D04.L2 | v454.02,165.1 449.58,165.1 D05.P2
N$287  (via drill 0.61)
  Top 0.254: v466.73,220.98 466.73,247.01 | 466.73,247.01 462.28,251.46 462.28,253.36 C04.H2 | v470.54,293.37 466.73,289.56 466.73,247.01
  Bottom 0.254: v466.73,220.98 460.38,220.98 459.11,219.71 C04.V2 | C05.H2 449.58,254.63 450.21,255.27 454.66,255.27 455.3,255.91 458.47,255.91 459.74,254.63 461.64,254.63 C04.H2 | v470.54,293.37 473.07,293.37 474.35,294.64 B03.S2
N$288  (via drill 0.61)
  Top 0.254: v450.85,229.87 450.85,241.94 449.58,243.2 449.58,247.01 C05.K2 | v455.3,311.15 454.02,309.88 454.02,286.39 457.2,283.21 v457.2,249.56
  Route2 0.254: B03.P2 474.35,302.26 474.35,304.17 472.44,306.07 468,306.07 467.36,306.71 459.11,306.71 459.11,310.52 B04.L2 458.47,311.15 v455.3,311.15
  Bottom 0.254: v450.85,229.87 454.66,229.87 455.3,230.5 460.38,230.5 461.64,229.23 C04.S2 | v457.2,249.56 453.39,249.56 452.12,248.28 449.58,248.28 C05.K2
N$289  (via drill 0.61)
  Top 0.254: v448.94,285.12 447.68,283.85 447.68,240.66 448.31,240.03 448.31,236.22 448.94,235.59 C05.P2 | v476.25,298.45 476.25,312.42 474.98,313.69 B03.K2 474.35,314.96 473.07,316.23 473.07,340.36 v471.17,342.27
  Route3 0.254: v457.2,342.9 457.2,357.5 460.38,360.68 460.38,375.29 459.74,375.92 459.74,379.73 459.11,380.37 A04.L2
  Bottom 0.254: v448.94,285.12 444.5,289.56 444.5,296.55 454.66,296.55 455.3,297.18 460.38,297.18 461.64,295.91 B04.S2 462.28,295.91 464.82,295.91 466.09,297.18 474.98,297.18 v476.25,298.45 | v457.2,342.9 457.83,342.27 v471.17,342.27
N$290  (via drill 0.61)
  Top 0.254: v451.49,242.57 450.85,243.2 v450.85,314.33 | v474.35,316.23 474.35,320.04 B03.H2 | v457.2,316.87 457.2,337.19 458.47,338.46 458.47,354.97 A04.V2 458.47,356.24 457.83,356.87 457.83,358.78 454.02,362.59 454.02,384.81 v456.56,387.35
  Route3 0.254: v451.49,242.57 451.49,241.3 447.68,237.49 447.68,234.31 448.31,233.68 448.31,229.87 448.94,229.23 C05.S2
  Bottom 0.254: v450.85,314.33 452.12,315.6 454.66,315.6 455.3,316.23 457.2,316.23 | 457.2,316.23 464.19,316.23 464.82,315.6 467.36,315.6 468,316.23 v474.35,316.23 | 457.2,316.23 v457.2,316.87 | v456.56,387.35 459.11,389.89 461.64,389.89 A04.H2
N$291  (via drill 0.61)
  Top 0.254: v478.15,288.93 473.07,294 473.07,314.96 471.81,316.23 471.81,316.87 B03.J2
  Route2 0.254: v478.15,288.93 480.06,287.02 483.24,287.02 483.87,286.39 B02.V2
N$293  (via drill 0.61)
  Route3 0.254: v460.38,265.43 460.38,281.94 454.02,288.29 454.02,335.92 460.38,342.27 460.38,359.41 461.64,360.68 461.64,364.49 A04.S2
  Bottom 0.254: v460.38,265.43 458.47,265.43 454.66,261.62 450.21,261.62 449.58,260.99 C05.E2
N$294  (via drill 0.61)
  Top 0.254: v484.5,309.25 485.77,307.98 485.77,300.36 485.14,299.72 488.95,295.91 488.95,256.54 487.68,255.27 487.68,254.63 C02.H2
  Bottom 0.254: v484.5,309.25 483.87,309.88 480.69,309.88 480.06,309.25 477.52,309.25 476.88,309.88 472.44,309.88 471.81,310.52 B03.L2
N$295  (via drill 0.61)
  Top 0.254: v474.35,291.47 476.25,289.56 476.25,284.48 476.88,283.85 476.88,273.05 479.43,270.51 479.43,257.81 482.6,254.63 v482.6,242.57
  Route2 0.254: v474.35,291.47 465.45,300.36 464.19,300.36 464.19,301.62 466.09,303.53 470.54,303.53 471.17,304.17 B03.N2
  Bottom 0.254: v482.6,242.57 483.24,241.94 487.05,241.94 C02.M2
N$296  (via drill 0.61)
  Top 0.254: v474.35,298.45 482.6,290.2 482.6,255.91 485.77,252.73 485.77,230.5 487.05,229.23 C02.S2
  Route2 0.254: v474.35,298.45 471.81,298.45 B03.R2
N$297  (via drill 0.61)
  Top 0.254: v468.63,192.41 466.73,194.31 466.73,219.71 463.55,222.88 463.55,240.66 v465.45,242.57
  Route3 0.254: v465.45,242.57 466.73,243.84 466.73,285.12 471.17,289.56 471.17,291.47 B03.T2
  Bottom 0.254: v468.63,192.41 469.26,191.77 478.15,191.77 478.79,192.41 481.33,192.41 483.24,190.5 487.05,190.5 D02.E2
N$298  (via drill 0.61)
  Top 0.254: v477.52,223.52 481.96,219.07 481.96,206.38 479.43,203.84 479.43,195.58 v481.33,193.67 | v483.87,191.77 483.87,187.96 D02.F2
  Route2 0.254: v481.33,193.67 483.24,191.77 v483.87,191.77
  Route3 0.254: v474.35,219.07 473.07,220.34 473.07,276.86 471.81,278.13 471.81,285.12 B03.V2
  Bottom 0.254: v474.35,219.07 476.25,220.98 476.25,223.52 v477.52,223.52
N$299  (via drill 0.61)
  Route2 0.254: v479.43,184.15 479.43,182.88 483.87,178.44 483.87,175.26 D02.L2
  Bottom 0.254: v479.43,184.15 478.15,185.42 476.25,185.42 474.35,187.32 471.81,187.32 D03.F2
N$300  (via drill 0.61)
  Top 0.254: v478.15,163.83 470.54,171.45 470.54,173.35 469.9,173.99 469.9,179.07 471.17,180.34 D03.J2
  Bottom 0.254: v478.15,163.83 478.79,163.19 483.24,163.19 483.87,162.56 D02.R2
N$301  (via drill 0.61)
  Top 0.254: v480.69,120.65 479.43,121.92 v479.43,168.28
  Bottom 0.254: v480.69,120.65 481.96,121.92 483.87,121.92 483.87,126.36 E02.D2 | v479.43,168.28 479.43,172.72 473.07,172.72 471.81,173.99 D03.L2
N$302  (via drill 0.61)
  Top 0.254: v488.95,144.78 488.95,119.38 487.68,118.11 E02.H2 | v474.98,146.05 473.07,147.95 473.07,166.37 471.81,167.64 D03.N2
  Bottom 0.254: v488.95,144.78 487.68,146.05 v474.98,146.05
N$303  (via drill 0.61)
  Top 0.254: v477.52,106.04 476.25,107.31 v476.25,161.29
  Bottom 0.254: v477.52,106.04 478.15,106.04 478.79,106.68 485.77,106.68 487.05,105.41 E02.M2 | v476.25,161.29 471.81,161.29 D03.R2
N$304  (via drill 0.61)
  Top 0.254: F04.P2 461.64,29.21 457.2,29.21 457.2,42.55 458.47,43.82 F04.J2 | v473.07,56.52 473.07,121.92 474.35,123.19 E03.E2
  Route2 0.254: v473.07,56.52 461.64,45.09 459.11,45.09 F04.J2
N$305  (via drill 0.61)
  Top 0.254: v454.02,119.38 454.02,19.69 458.47,19.69 F04.T2
  Bottom 0.254: v454.02,119.38 458.47,123.82 461.64,123.82 E04.E2 462.28,123.19 464.82,123.19 466.09,121.92 474.35,121.92 474.35,118.11 E03.H2
N$306  (via drill 0.61)
  Top 0.254: v458.47,103.5 457.2,104.77 457.2,112.39 458.47,113.66 E04.J2
  Bottom 0.254: v458.47,103.5 461.64,103.5 461.64,99.06 E04.P2 | E03.K2 474.35,111.76 473.07,113.03 466.09,113.03 465.45,112.39 460.38,112.39 459.11,113.66 E04.J2
N$307  (via drill 0.61)
  Top 0.254: v476.25,90.8 476.25,102.87 474.98,104.14 E03.M2 | v469.9,180.34 466.73,183.51 466.73,189.86 462.28,189.86 D04.E2 | v493.39,167.64 495.3,165.73 495.3,116.2 v493.39,114.3
  Bottom 0.254: v476.25,90.8 471.17,90.8 467.36,86.99 460.38,86.99 459.11,88.27 E04.T2 | v469.9,180.34 471.17,179.07 477.52,179.07 480.69,175.89 485.14,175.89 v493.39,167.64 | v493.39,114.3 488.31,109.22 478.79,109.22 478.15,109.85 477.52,109.85 474.98,107.31 474.98,105.41 E03.M2
N$308  (via drill 0.61)
  Top 0.254: v443.23,167 443.23,169.54 444.5,170.81 v444.5,227.97 | v461.01,233.04 460.38,233.68 460.38,242.57 v462.28,244.47 | v495.3,353.7 495.3,318.14 492.12,314.96 492.12,305.44 495.3,302.26 v495.3,301.62 | v465.45,287.66 463.55,287.66 463.55,262.25 462.28,260.99 C04.E2
  Route3 0.254: v462.28,244.47 460.38,246.38 460.38,258.44 461.64,259.72 C04.E2
  Bottom 0.254: v443.23,167 446.4,163.83 452.75,163.83 455.93,160.66 463.55,160.66 463.55,158.11 462.92,157.48 460.38,157.48 459.11,156.21 D04.T2 | v444.5,227.97 448.31,231.78 450.21,231.78 452.12,233.68 454.66,233.68 455.3,233.04 v461.01,233.04 | v495.3,353.7 483.87,353.7 480.06,357.5 475.62,357.5 474.98,358.14 A03.U2 | v495.3,301.62 495.3,290.83 491.49,290.83 490.86,290.2 481.96,290.2 481.33,290.83 478.79,290.83 474.98,287.02 466.09,287.02 v465.45,287.66
N$309  (via drill 0.61)
  Top 0.254: v468.63,100.33 466.73,102.23 466.73,156.84 462.28,161.29 462.28,164.47 D04.P2 | v457.2,165.1 457.2,175.26 457.83,175.89 457.83,179.7 458.47,180.34 D04.J2
  Bottom 0.254: v468.63,100.33 473.07,100.33 474.35,99.06 E03.P2 | v457.2,165.1 461.64,165.1 D04.P2
N$310  (via drill 0.61)
  Top 0.254: v457.2,235.59 457.2,248.28 458.47,249.56 458.47,250.19 C04.J2
  Route2 0.254: v457.2,235.59 461.64,235.59 C04.P2 | v457.2,286.39 457.2,258.44 459.74,258.44 460.38,257.81 460.38,251.46 459.11,251.46 C04.J2
  Route3 0.254: v457.2,286.39 457.2,294.64 466.73,304.17 466.73,321.31 467.36,321.95 467.36,322.58 476.25,331.47 476.25,363.22 474.98,364.49 A03.S2
N$311  (via drill 0.61)
  Top 0.254: v438.15,325.75 v438.15,228.6 | v469.9,328.3 469.9,342.27 476.25,348.62 476.25,369.57 474.98,370.84 A03.P2
  Bottom 0.254: v438.15,228.6 438.79,228.6 440.69,226.69 444.5,226.69 445.13,227.33 452.75,227.33 453.39,226.69 457.83,226.69 458.47,226.06 C04.T2 | v438.15,325.75 441.96,325.75 442.6,325.12 451.49,325.12 452.12,325.75 454.66,325.75 455.3,325.12 460.38,325.12 461.64,326.39 B04.E2 462.28,327.66 466.09,327.66 467.36,328.93 469.26,328.93 v469.9,328.3
N$312  (via drill 0.61)
  Top 0.254: 457.2,315.6 458.47,316.87 B04.J2 | 457.2,315.6 v457.2,301.62 | v473.07,350.52 473.07,375.92 474.35,377.19 A03.M2 | v455.93,350.52 454.02,348.62 454.02,318.77 457.2,315.6
  Bottom 0.254: v457.2,301.62 461.64,301.62 B04.P2 | v473.07,350.52 472.44,351.16 456.56,351.16 v455.93,350.52
N$313  (via drill 0.61)
  Top 0.254: v464.82,294 466.73,295.91 466.73,374.02 471.17,378.46 | 471.17,378.46 474.35,381.64 474.35,383.54 A03.K2 | 471.17,378.46 463.55,386.08 463.55,394.97 462.28,396.24 A04.E2
  Bottom 0.254: v464.82,294 460.38,294 459.11,292.74 B04.T2
N$314  (via drill 0.61)
  Top 0.254: v459.11,371.48 457.2,373.38 457.2,385.45 458.47,386.72 A04.J2
  Route2 0.254: v459.11,371.48 461.64,371.48 A04.P2
  Bottom 0.254: A03.H2 474.35,389.89 473.07,388.62 466.09,388.62 465.45,389.25 460.38,389.25 459.11,387.99 A04.J2
N$315  (via drill 0.61)
  Top 0.254: 460.38,33.66 459.11,32.38 F04.N2 | 460.38,39.37 460.38,33.66 | 460.38,39.37 461.64,40.64 F04.K2 | 460.38,39.37 460.38,51.44 459.74,52.07 459.74,55.88 459.11,56.52 F04.D2 458.47,57.79 457.2,59.05 457.2,78.74 461.64,83.18 461.64,85.09 E04.U2 461.64,86.36 460.38,87.63 460.38,96.52 459.11,97.79 459.11,100.96 E04.N2 459.11,102.23 460.38,103.5 460.38,109.22 | F09.V2 395.61,12.06 395.61,3.17 398.14,0.63 461.64,0.63 461.64,15.24 F04.U2 462.28,16.51 463.55,17.78 463.55,30.48 460.38,33.66 | 460.38,175.89 460.38,170.18 459.11,168.91 D04.N2 459.11,167.64 459.11,164.47 460.38,163.19 460.38,154.31 461.64,153.03 D04.U2 461.64,151.76 460.38,150.5 460.38,130.18 459.11,128.91 459.11,127.63 E04.D2 459.11,126.36 459.11,122.55 460.38,121.28 460.38,109.22 | 460.38,175.89 461.64,177.16 D04.K2 | 460.38,175.89 460.38,187.96 459.74,188.59 459.74,192.41 459.11,193.04 D04.D2 459.11,194.31 459.11,198.12 460.38,199.39 460.38,217.17 461.64,218.44 461.64,221.61 C04.U2 461.64,222.88 460.38,224.16 460.38,232.41 459.11,233.68 459.11,237.49 C04.N2 459.11,238.76 459.74,239.39 459.74,243.2 460.38,243.84 | E08.V2 408.31,83.18 409.57,84.45 409.57,112.39 408.31,113.66 E08.J2 | 460.38,109.22 461.64,110.49 E04.K2 | v288.93,340.36 v288.93,308.61 | v310.51,341 311.15,341.63 311.15,382.27 309.88,383.54 A16.K2 309.88,384.81 311.15,386.08 v311.15,421 | 460.38,382.27 460.38,376.56 459.11,375.29 A04.N2 459.11,374.02 460.38,372.75 460.38,360.68 461.64,359.41 A04.U2 461.64,358.14 460.38,356.87 460.38,328.3 | 460.38,382.27 461.64,383.54 A04.K2 | 460.38,398.15 459.11,399.42 A04.D2
  Top 0.254: 460.38,382.27 460.38,398.15 | 460.38,243.84 461.64,245.11 461.64,247.01 C04.K2 | 460.38,243.84 460.38,261.62 459.11,262.89 C04.D2 459.11,264.16 459.11,267.97 460.38,269.24 460.38,290.83 | 460.38,306.71 459.11,305.44 B04.N2 | 460.38,306.71 460.38,312.42 | 460.38,312.42 461.64,313.69 B04.K2 | 460.38,328.3 459.11,329.56 B04.D2 | 460.38,312.42 460.38,328.3 | 460.38,290.83 461.64,289.56 B04.U2 | 460.38,290.83 460.38,306.71 | v448.31,420.37 460.38,408.31 460.38,398.15
  Route3 0.254: v408.31,80.01 408.31,81.91 E08.V2
  Bottom 0.254: v408.31,80.01 466.09,80.01 466.73,79.38 468,80.64 468,83.82 466.09,83.82 464.82,85.09 462.28,85.09 E04.U2 | v288.93,308.61 284.48,308.61 B18.M2 | v288.93,340.36 290.19,341.63 309.88,341.63 v310.51,341 | v311.15,421 311.79,421.64 447.04,421.64 v448.31,420.37
N$317  (via drill 0.61)
  Top 0.254: v452.75,246.38 454.02,247.65 v454.02,285.12 | 463.55,307.98 v463.55,288.93 | 463.55,307.98 463.55,318.77 462.28,320.04 B04.H2 | 463.55,307.98 v465.45,307.98
  Bottom 0.254: v452.75,246.38 449.58,246.38 449.58,241.94 C05.M2 | v454.02,285.12 458.47,285.12 B04.V2 459.11,286.39 463.55,286.39 v463.55,288.93 | v465.45,307.98 467.36,306.07 473.07,306.07 474.35,307.34 B03.M2
N$318  (via drill 0.61)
